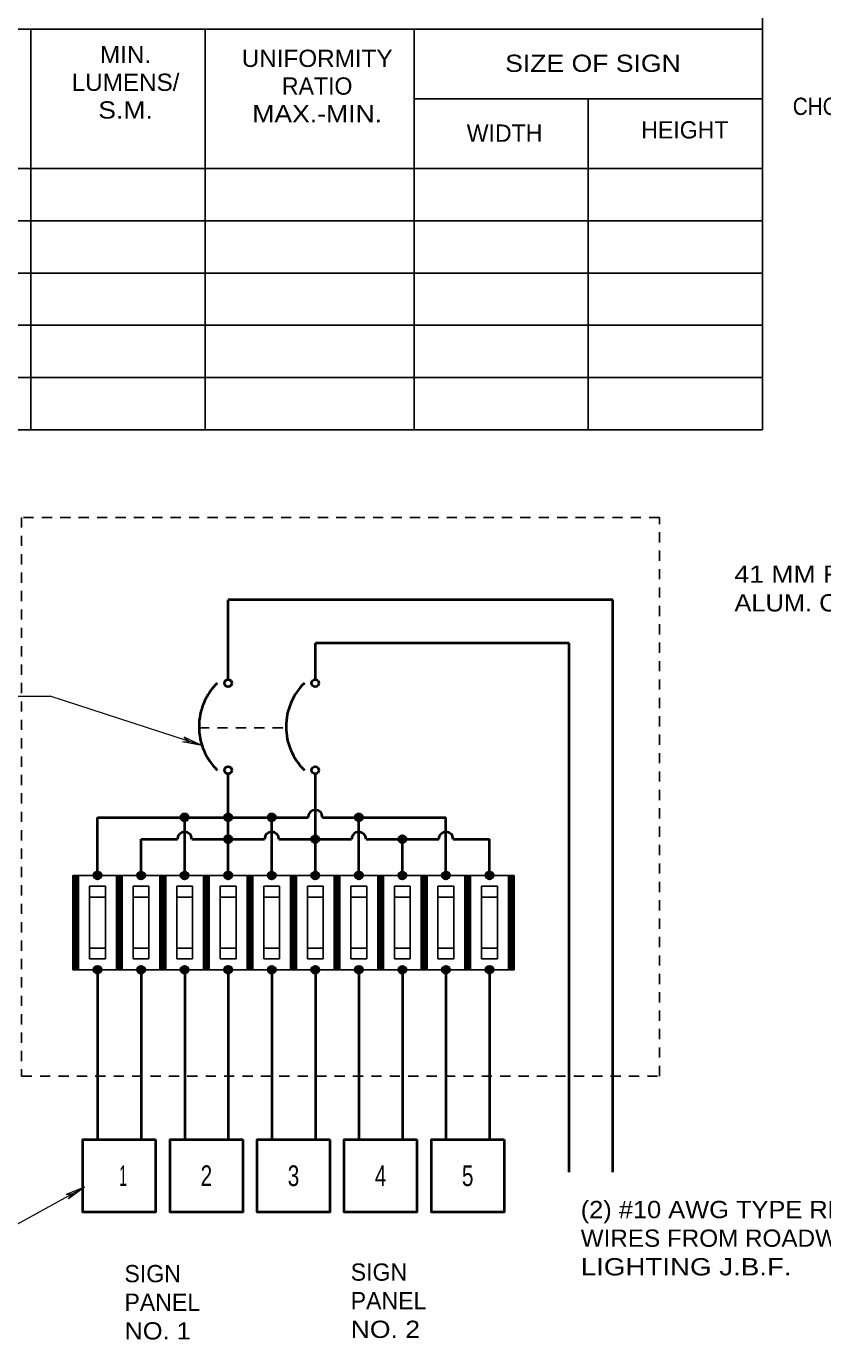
# Model space of a CAD drawing. Extents: x 312583 to 312854, y 144419 to 144597.
# Drawn here: x 312640.4 to 312675.5, y 144479 to 144536.8 of the extents above; entities that cross this region are included whole.
import ezdxf
from ezdxf.enums import TextEntityAlignment as Align

# ---------------------------------------------------------------- set-up
doc = ezdxf.new("R2010")
doc.units = 0
doc.header["$LTSCALE"] = 0.3
doc.linetypes.add('SHORT_DASHED', pattern=[2.7, 1.5, -1.2])
doc.layers.add('1', color=7, linetype='Continuous', lineweight=13)

msp = doc.modelspace()

# ---------------------------------------------------------------- linework, layer by layer
at = {"layer": '1', "lineweight": 25}
for p, q in [((312672.8219, 144540.3271), (312672.8219, 144519.0521)), ((312623.7553, 144536.6855), (312672.8219, 144536.6855)), ((312640.6219, 144536.6855), (312640.6219, 144519.0521)), ((312648.2886, 144536.6855), (312648.2886, 144519.0521)), ((312657.4886, 144536.6855), (312657.4886, 144519.0521)), ((312657.4886, 144533.6188), (312672.8219, 144533.6188)), ((312665.1553, 144533.6188), (312665.1553, 144519.0521)), ((312623.7553, 144530.5521), (312672.8219, 144530.5521)), ((312623.7553, 144528.2521), (312672.8219, 144528.2521)), ((312623.7553, 144525.9521), (312672.8219, 144525.9521)), ((312623.7553, 144523.6521), (312672.8219, 144523.6521)), ((312623.7553, 144521.3521), (312672.8219, 144521.3521)), ((312623.7553, 144519.0521), (312672.8219, 144519.0521)), ((312642.4699, 144499.4355), (312652.3062, 144499.4355)), ((312642.4699, 144495.2802), (312642.4699, 144499.4355)), ((312642.5312, 144495.2802), (312642.5312, 144499.4355)), ((312642.6002, 144495.2802), (312642.6002, 144499.4355)), ((312642.6615, 144495.2802), (312642.6615, 144499.4355)), ((312642.7229, 144495.2802), (312642.7229, 144499.4355)), ((312644.3865, 144495.2802), (312644.3865, 144499.4355)), ((312644.4479, 144495.2802), (312644.4479, 144499.4355)), ((312644.5169, 144495.2802), (312644.5169, 144499.4355)), ((312644.5782, 144495.2802), (312644.5782, 144499.4355)), ((312644.6395, 144495.2802), (312644.6395, 144499.4355)), ((312646.3032, 144495.2802), (312646.3032, 144499.4355)), ((312646.3645, 144495.2802), (312646.3645, 144499.4355)), ((312646.4335, 144495.2802), (312646.4335, 144499.4355)), ((312646.4949, 144495.2802), (312646.4949, 144499.4355)), ((312646.5562, 144495.2802), (312646.5562, 144499.4355)), ((312648.2199, 144495.2802), (312648.2199, 144499.4355)), ((312648.2812, 144495.2802), (312648.2812, 144499.4355)), ((312648.3502, 144495.2802), (312648.3502, 144499.4355)), ((312648.4115, 144495.2802), (312648.4115, 144499.4355)), ((312648.4729, 144495.2802), (312648.4729, 144499.4355)), ((312650.1365, 144495.2802), (312650.1365, 144499.4355)), ((312650.1979, 144495.2802), (312650.1979, 144499.4355)), ((312650.2669, 144495.2802), (312650.2669, 144499.4355)), ((312650.3282, 144495.2802), (312650.3282, 144499.4355)), ((312650.3895, 144495.2802), (312650.3895, 144499.4355)), ((312652.0532, 144495.2802), (312652.0532, 144499.4355)), ((312652.0532, 144499.4355), (312661.8895, 144499.4355)), ((312652.1145, 144495.2802), (312652.1145, 144499.4355)), ((312652.1835, 144495.2802), (312652.1835, 144499.4355)), ((312652.2449, 144495.2802), (312652.2449, 144499.4355)), ((312652.3062, 144495.2802), (312652.3062, 144499.4355)), ((312653.9699, 144495.2802), (312653.9699, 144499.4355)), ((312654.0312, 144495.2802), (312654.0312, 144499.4355)), ((312654.1002, 144495.2802), (312654.1002, 144499.4355)), ((312654.1615, 144495.2802), (312654.1615, 144499.4355)), ((312654.2229, 144495.2802), (312654.2229, 144499.4355)), ((312655.8865, 144495.2802), (312655.8865, 144499.4355)), ((312655.9479, 144495.2802), (312655.9479, 144499.4355)), ((312656.0169, 144495.2802), (312656.0169, 144499.4355)), ((312656.0782, 144495.2802), (312656.0782, 144499.4355)), ((312656.1395, 144495.2802), (312656.1395, 144499.4355)), ((312657.8032, 144495.2802), (312657.8032, 144499.4355)), ((312657.8645, 144495.2802), (312657.8645, 144499.4355)), ((312657.9335, 144495.2802), (312657.9335, 144499.4355)), ((312657.9949, 144495.2802), (312657.9949, 144499.4355)), ((312658.0562, 144495.2802), (312658.0562, 144499.4355)), ((312659.7199, 144495.2802), (312659.7199, 144499.4355)), ((312659.7812, 144495.2802), (312659.7812, 144499.4355)), ((312659.8502, 144495.2802), (312659.8502, 144499.4355)), ((312659.9115, 144495.2802), (312659.9115, 144499.4355)), ((312659.9729, 144495.2802), (312659.9729, 144499.4355)), ((312661.6365, 144495.2802), (312661.6365, 144499.4355)), ((312661.6979, 144495.2802), (312661.6979, 144499.4355)), ((312661.7669, 144495.2802), (312661.7669, 144499.4355)), ((312661.8282, 144495.2802), (312661.8282, 144499.4355)), ((312661.8895, 144495.2802), (312661.8895, 144499.4355)), ((312643.2059, 144498.9602), (312643.9035, 144498.9602)), ((312643.2059, 144495.7632), (312643.2059, 144498.9602)), ((312643.9035, 144495.7632), (312643.9035, 144498.9602)), ((312645.1225, 144498.9602), (312645.8202, 144498.9602)), ((312645.1225, 144495.7632), (312645.1225, 144498.9602)), ((312645.8202, 144495.7632), (312645.8202, 144498.9602)), ((312647.0392, 144498.9602), (312647.7369, 144498.9602)), ((312647.0392, 144495.7632), (312647.0392, 144498.9602)), ((312647.7369, 144495.7632), (312647.7369, 144498.9602)), ((312648.9559, 144498.9602), (312649.6535, 144498.9602)), ((312648.9559, 144495.7632), (312648.9559, 144498.9602)), ((312649.6535, 144495.7632), (312649.6535, 144498.9602)), ((312650.8725, 144498.9602), (312651.5702, 144498.9602)), ((312650.8725, 144495.7632), (312650.8725, 144498.9602)), ((312651.5702, 144495.7632), (312651.5702, 144498.9602)), ((312652.7892, 144498.9602), (312653.4869, 144498.9602)), ((312652.7892, 144495.7632), (312652.7892, 144498.9602)), ((312653.4869, 144495.7632), (312653.4869, 144498.9602)), ((312654.7059, 144498.9602), (312655.4035, 144498.9602)), ((312654.7059, 144495.7632), (312654.7059, 144498.9602)), ((312655.4035, 144495.7632), (312655.4035, 144498.9602)), ((312656.6225, 144498.9602), (312657.3202, 144498.9602)), ((312656.6225, 144495.7632), (312656.6225, 144498.9602)), ((312657.3202, 144495.7632), (312657.3202, 144498.9602)), ((312658.5392, 144498.9602), (312659.2369, 144498.9602)), ((312658.5392, 144495.7632), (312658.5392, 144498.9602)), ((312659.2369, 144495.7632), (312659.2369, 144498.9602)), ((312660.4559, 144498.9602), (312661.1535, 144498.9602)), ((312660.4559, 144495.7632), (312660.4559, 144498.9602)), ((312661.1535, 144495.7632), (312661.1535, 144498.9602)), ((312643.2059, 144498.4772), (312643.9035, 144498.4772)), ((312645.1225, 144498.4772), (312645.8202, 144498.4772)), ((312647.0392, 144498.4772), (312647.7369, 144498.4772)), ((312648.9559, 144498.4772), (312649.6535, 144498.4772)), ((312650.8725, 144498.4772), (312651.5702, 144498.4772)), ((312652.7892, 144498.4772), (312653.4869, 144498.4772)), ((312654.7059, 144498.4772), (312655.4035, 144498.4772)), ((312656.6225, 144498.4772), (312657.3202, 144498.4772)), ((312658.5392, 144498.4772), (312659.2369, 144498.4772)), ((312660.4559, 144498.4772), (312661.1535, 144498.4772)), ((312643.2059, 144496.2385), (312643.9035, 144496.2385)), ((312645.1225, 144496.2385), (312645.8202, 144496.2385)), ((312647.0392, 144496.2385), (312647.7369, 144496.2385)), ((312648.9559, 144496.2385), (312649.6535, 144496.2385)), ((312650.8725, 144496.2385), (312651.5702, 144496.2385)), ((312652.7892, 144496.2385), (312653.4869, 144496.2385)), ((312654.7059, 144496.2385), (312655.4035, 144496.2385)), ((312656.6225, 144496.2385), (312657.3202, 144496.2385)), ((312658.5392, 144496.2385), (312659.2369, 144496.2385)), ((312660.4559, 144496.2385), (312661.1535, 144496.2385)), ((312643.2059, 144495.7632), (312643.9035, 144495.7632)), ((312645.1225, 144495.7632), (312645.8202, 144495.7632)), ((312647.0392, 144495.7632), (312647.7369, 144495.7632)), ((312648.9559, 144495.7632), (312649.6535, 144495.7632)), ((312650.8725, 144495.7632), (312651.5702, 144495.7632)), ((312652.7892, 144495.7632), (312653.4869, 144495.7632)), ((312654.7059, 144495.7632), (312655.4035, 144495.7632)), ((312656.6225, 144495.7632), (312657.3202, 144495.7632)), ((312658.5392, 144495.7632), (312659.2369, 144495.7632)), ((312660.4559, 144495.7632), (312661.1535, 144495.7632)), ((312642.4699, 144495.2802), (312652.3062, 144495.2802)), ((312652.0532, 144495.2802), (312661.8895, 144495.2802))]:
    msp.add_line(p, q, dxfattribs=at)
at = {"layer": '1', "linetype": 'SHORT_DASHED', "lineweight": 25}
for p, q in [((312668.2835, 144490.6035), (312668.2835, 144515.1982)), ((312648.0205, 144505.9292), (312651.8539, 144505.9292)), ((312640.2159, 144490.6035), (312668.2835, 144490.6035))]:
    msp.add_line(p, q, dxfattribs=at)
at = {"layer": '1', "lineweight": 40}
for p, q in [((312649.3085, 144508.0605), (312649.3085, 144511.5718)), ((312666.2365, 144511.5718), (312649.3085, 144511.5718)), ((312666.2365, 144486.3715), (312666.2365, 144511.5718)), ((312653.1419, 144508.0605), (312653.1419, 144509.6552)), ((312664.3199, 144509.6552), (312653.1419, 144509.6552)), ((312664.3199, 144486.3715), (312664.3199, 144509.6552)), ((312649.3085, 144501.9885), (312649.3085, 144503.9052)), ((312649.3085, 144501.0302), (312649.3085, 144503.9052)), ((312653.1419, 144499.4355), (312653.1419, 144503.9052)), ((312643.5585, 144501.9885), (312649.3085, 144501.9885)), ((312643.5585, 144499.4355), (312643.5585, 144501.9885)), ((312647.2309, 144501.9885), (312647.5452, 144501.9885)), ((312647.2769, 144501.8812), (312647.4992, 144502.1035)), ((312647.4992, 144501.8812), (312647.2769, 144502.1035)), ((312647.3919, 144501.8352), (312647.3919, 144502.1495)), ((312647.3919, 144499.4355), (312647.3919, 144501.9885)), ((312649.1475, 144501.9885), (312649.4619, 144501.9885)), ((312649.1935, 144501.8812), (312649.4159, 144502.1035)), ((312649.4159, 144501.8812), (312649.1935, 144502.1035)), ((312649.3085, 144501.8352), (312649.3085, 144502.1495)), ((312649.3085, 144501.9885), (312652.8199, 144501.9885)), ((312651.0642, 144501.9885), (312651.3785, 144501.9885)), ((312651.1102, 144501.8812), (312651.3325, 144502.1035)), ((312651.3325, 144501.8812), (312651.1102, 144502.1035)), ((312651.2252, 144501.8352), (312651.2252, 144502.1495)), ((312651.2252, 144499.4355), (312651.2252, 144501.9885)), ((312653.4562, 144501.9885), (312658.8919, 144501.9885)), ((312654.8975, 144501.9885), (312655.2119, 144501.9885)), ((312654.9435, 144501.8812), (312655.1659, 144502.1035)), ((312655.1659, 144501.8812), (312654.9435, 144502.1035)), ((312655.0585, 144501.8352), (312655.0585, 144502.1495)), ((312655.0585, 144499.4355), (312655.0585, 144501.9885)), ((312658.8919, 144499.4355), (312658.8919, 144501.9885)), ((312649.1935, 144500.9228), (312649.4159, 144501.1452)), ((312649.4159, 144500.9228), (312649.1935, 144501.1452)), ((312649.3085, 144500.8768), (312649.3085, 144501.1912)), ((312653.0269, 144500.9228), (312653.2492, 144501.1452)), ((312653.2492, 144500.9228), (312653.0269, 144501.1452)), ((312653.1419, 144500.8768), (312653.1419, 144501.1912)), ((312656.8602, 144500.9228), (312657.0825, 144501.1452)), ((312657.0825, 144500.9228), (312656.8602, 144501.1452)), ((312656.9752, 144500.8768), (312656.9752, 144501.1912)), ((312645.4752, 144499.4355), (312645.4752, 144501.0302)), ((312645.4752, 144501.0302), (312647.0699, 144501.0302)), ((312647.7062, 144501.0302), (312650.9032, 144501.0302)), ((312649.1475, 144501.0302), (312649.4619, 144501.0302)), ((312649.3085, 144499.4355), (312649.3085, 144501.0302)), ((312651.5395, 144501.0302), (312654.7365, 144501.0302)), ((312652.9809, 144501.0302), (312653.2952, 144501.0302)), ((312655.3729, 144501.0302), (312658.5699, 144501.0302)), ((312656.8142, 144501.0302), (312657.1285, 144501.0302)), ((312656.9752, 144499.4355), (312656.9752, 144501.0302)), ((312659.2062, 144501.0302), (312660.8085, 144501.0302)), ((312660.8085, 144499.4355), (312660.8085, 144501.0302)), ((312643.3975, 144499.4355), (312643.7119, 144499.4355)), ((312643.4435, 144499.3205), (312643.6659, 144499.5505)), ((312643.6659, 144499.3205), (312643.4435, 144499.5505)), ((312643.5585, 144499.2745), (312643.5585, 144499.5965)), ((312645.3142, 144499.4355), (312645.6285, 144499.4355)), ((312645.3602, 144499.3205), (312645.5825, 144499.5505)), ((312645.5825, 144499.3205), (312645.3602, 144499.5505)), ((312645.4752, 144499.2745), (312645.4752, 144499.5965)), ((312647.2309, 144499.4355), (312647.5452, 144499.4355)), ((312647.2769, 144499.3205), (312647.4992, 144499.5505)), ((312647.4992, 144499.3205), (312647.2769, 144499.5505)), ((312647.3919, 144499.2745), (312647.3919, 144499.5965)), ((312649.1475, 144499.4355), (312649.4619, 144499.4355)), ((312649.1935, 144499.3205), (312649.4159, 144499.5505)), ((312649.4159, 144499.3205), (312649.1935, 144499.5505)), ((312649.3085, 144499.2745), (312649.3085, 144499.5965)), ((312651.0642, 144499.4355), (312651.3785, 144499.4355)), ((312651.1102, 144499.3205), (312651.3325, 144499.5505)), ((312651.3325, 144499.3205), (312651.1102, 144499.5505)), ((312651.2252, 144499.2745), (312651.2252, 144499.5965)), ((312652.9809, 144499.4355), (312653.2952, 144499.4355)), ((312653.0269, 144499.3205), (312653.2492, 144499.5505)), ((312653.2492, 144499.3205), (312653.0269, 144499.5505)), ((312653.1419, 144499.2745), (312653.1419, 144499.5965)), ((312654.8975, 144499.4355), (312655.2119, 144499.4355)), ((312654.9435, 144499.3205), (312655.1659, 144499.5505)), ((312655.1659, 144499.3205), (312654.9435, 144499.5505)), ((312655.0585, 144499.2745), (312655.0585, 144499.5965)), ((312656.8142, 144499.4355), (312657.1285, 144499.4355)), ((312656.8602, 144499.3205), (312657.0825, 144499.5505)), ((312657.0825, 144499.3205), (312656.8602, 144499.5505)), ((312656.9752, 144499.2745), (312656.9752, 144499.5965)), ((312658.7309, 144499.4355), (312659.0452, 144499.4355)), ((312658.7769, 144499.3205), (312658.9992, 144499.5505)), ((312658.9992, 144499.3205), (312658.7769, 144499.5505)), ((312658.8919, 144499.2745), (312658.8919, 144499.5965)), ((312660.6475, 144499.4355), (312660.9619, 144499.4355)), ((312660.6935, 144499.3205), (312660.9159, 144499.5505)), ((312660.9159, 144499.3205), (312660.6935, 144499.5505)), ((312660.8085, 144499.2745), (312660.8085, 144499.5965)), ((312643.4435, 144495.1728), (312643.6659, 144495.3952)), ((312643.6659, 144495.1728), (312643.4435, 144495.3952)), ((312643.5585, 144495.1268), (312643.5585, 144495.4412)), ((312645.3602, 144495.1728), (312645.5825, 144495.3952)), ((312645.5825, 144495.1728), (312645.3602, 144495.3952)), ((312645.4752, 144495.1268), (312645.4752, 144495.4412)), ((312647.2769, 144495.1728), (312647.4992, 144495.3952)), ((312647.4992, 144495.1728), (312647.2769, 144495.3952)), ((312647.3919, 144495.1268), (312647.3919, 144495.4412)), ((312649.1935, 144495.1728), (312649.4159, 144495.3952)), ((312649.4159, 144495.1728), (312649.1935, 144495.3952)), ((312649.3085, 144495.1268), (312649.3085, 144495.4412)), ((312651.1102, 144495.1728), (312651.3325, 144495.3952)), ((312651.3325, 144495.1728), (312651.1102, 144495.3952)), ((312651.2252, 144495.1268), (312651.2252, 144495.4412)), ((312653.0269, 144495.1728), (312653.2492, 144495.3952)), ((312653.2492, 144495.1728), (312653.0269, 144495.3952)), ((312653.1419, 144495.1268), (312653.1419, 144495.4412)), ((312654.9435, 144495.1728), (312655.1659, 144495.3952)), ((312655.1659, 144495.1728), (312654.9435, 144495.3952)), ((312655.0585, 144495.1268), (312655.0585, 144495.4412)), ((312656.8602, 144495.1728), (312657.0825, 144495.3952)), ((312657.0825, 144495.1728), (312656.8602, 144495.3952)), ((312656.9752, 144495.1268), (312656.9752, 144495.4412)), ((312658.7769, 144495.1728), (312658.9992, 144495.3952)), ((312658.9992, 144495.1728), (312658.7769, 144495.3952)), ((312658.8919, 144495.1268), (312658.8919, 144495.4412)), ((312660.6935, 144495.1728), (312660.9159, 144495.3952)), ((312660.9159, 144495.1728), (312660.6935, 144495.3952)), ((312660.8085, 144495.1268), (312660.8085, 144495.4412)), ((312643.3975, 144495.2802), (312643.7119, 144495.2802)), ((312643.5585, 144495.2802), (312643.5585, 144487.8052)), ((312645.3142, 144495.2802), (312645.6285, 144495.2802)), ((312645.4752, 144495.2802), (312645.4752, 144487.8052)), ((312647.2309, 144495.2802), (312647.5452, 144495.2802)), ((312647.3919, 144495.2802), (312647.3919, 144487.8052)), ((312649.1475, 144495.2802), (312649.4619, 144495.2802)), ((312649.3085, 144495.2802), (312649.3085, 144487.8052)), ((312651.0642, 144495.2802), (312651.3785, 144495.2802)), ((312651.2252, 144495.2802), (312651.2252, 144487.8052)), ((312652.9809, 144495.2802), (312653.2952, 144495.2802)), ((312653.1419, 144495.2802), (312653.1419, 144487.8052)), ((312654.8975, 144495.2802), (312655.2119, 144495.2802)), ((312655.0585, 144495.2802), (312655.0585, 144487.8052)), ((312656.8142, 144495.2802), (312657.1285, 144495.2802)), ((312656.9752, 144495.2802), (312656.9752, 144487.8052)), ((312658.7309, 144495.2802), (312659.0452, 144495.2802)), ((312658.8919, 144495.2802), (312658.8919, 144487.8052)), ((312660.6475, 144495.2802), (312660.9619, 144495.2802)), ((312660.8085, 144495.2802), (312660.8085, 144487.8052))]:
    msp.add_line(p, q, dxfattribs=at)
at = {"layer": '1'}
for p, q in [((312633.5919, 144507.3238), (312641.4655, 144507.3238)), ((312648.1509, 144505.1548), (312641.4655, 144507.3238)), ((312647.2999, 144505.3158), (312647.5912, 144505.3312)), ((312648.1509, 144505.1548), (312647.2999, 144505.3158)), ((312647.3612, 144505.5228), (312647.5912, 144505.3312)), ((312648.1509, 144505.1548), (312647.3612, 144505.5228)), ((312642.9835, 144485.7122), (312638.5675, 144483.2742)), ((312642.9835, 144485.7122), (312642.1785, 144485.3902)), ((312642.9835, 144485.7122), (312642.2782, 144485.1985)), ((312642.1785, 144485.3902), (312642.4699, 144485.4285)), ((312642.2782, 144485.1985), (312642.4699, 144485.4285))]:
    msp.add_line(p, q, dxfattribs=at)
at = {"layer": '1', "linetype": 'SHORT_DASHED', "lineweight": 25}
msp.add_lwpolyline([(312668.2835, 144515.1982), (312668.2835, 144515.1982), (312640.2159, 144515.1982), (312640.2159, 144490.6035)], dxfattribs=at)
at = {"layer": '1', "lineweight": 40}
for points in [[(312646.1115, 144487.8052), (312646.1115, 144484.6158), (312642.9145, 144484.6158), (312642.9145, 144487.8052)], [(312649.9449, 144487.8052), (312649.9449, 144484.6158), (312646.7479, 144484.6158), (312646.7479, 144487.8052)], [(312653.7782, 144487.8052), (312653.7782, 144484.6158), (312650.5812, 144484.6158), (312650.5812, 144487.8052)], [(312657.6115, 144487.8052), (312657.6115, 144484.6158), (312654.4145, 144484.6158), (312654.4145, 144487.8052)], [(312661.4449, 144487.8052), (312661.4449, 144484.6158), (312658.2479, 144484.6158), (312658.2479, 144487.8052)]]:
    msp.add_lwpolyline(points, close=True, dxfattribs=at)
for centre in [(312649.3047, 144507.9008), (312653.138, 144507.9008), (312649.3047, 144504.0674), (312653.138, 144504.0674), (312647.388, 144501.9911), (312649.3047, 144501.9911), (312651.2214, 144501.9911), (312655.0547, 144501.9911), (312649.3047, 144501.0327), (312653.138, 144501.0327), (312656.9714, 144501.0327), (312643.5547, 144499.4355), (312645.4714, 144499.4355), (312647.388, 144499.4355), (312649.3047, 144499.4355), (312651.2214, 144499.4355), (312653.138, 144499.4355), (312655.0547, 144499.4355), (312656.9714, 144499.4355), (312658.888, 144499.4355), (312660.8047, 144499.4355), (312643.5547, 144495.2827), (312645.4714, 144495.2827), (312647.388, 144495.2827), (312649.3047, 144495.2827), (312651.2214, 144495.2827), (312653.138, 144495.2827), (312655.0547, 144495.2827), (312656.9714, 144495.2827), (312658.888, 144495.2827), (312660.8047, 144495.2827)]:
    msp.add_circle(centre, 0.1597, dxfattribs=at)
for centre, radius, start, end in [((312650.7067, 144505.9841), 2.6856, 134.46426, 225.53573), ((312654.54, 144505.9841), 2.6856, 134.46426, 225.53573), ((312653.138, 144501.9911), 0.3194, 0, 180), ((312647.388, 144501.0327), 0.3194, 0, 180), ((312651.2214, 144501.0327), 0.3194, 0, 180), ((312655.0547, 144501.0327), 0.3194, 0, 180), ((312658.888, 144501.0327), 0.3194, 0, 180)]:
    msp.add_arc(centre, radius, start, end, dxfattribs=at)

# ---------------------------------------------------------------- texts
at = {"layer": '1'}
for s, height, width, p in [('MIN.', 0.76, 1.05, (312644.7888, 144535.1943)), ('UNIFORMITY', 0.76, 1.05, (312653.2221, 144535.0275)), ('SIZE OF SIGN', 0.76, 1.15, (312665.36, 144534.8092)), ('LUMENS/', 0.76, 1.05, (312644.7888, 144533.9743)), ('S.M.', 0.76, 1.15, (312644.7888, 144532.7543)), ('MAX.-MIN.', 0.76, 1.15, (312653.2221, 144532.5875)), ('1', 0.9104, 0.5, (312644.6817, 144485.7582)), ('2', 0.9104, 0.75, (312648.3463, 144485.7582)), ('3', 0.9104, 0.75, (312652.1797, 144485.7582)), ('4', 0.9104, 0.75, (312656.013, 144485.7582)), ('5', 0.9104, 0.75, (312659.8463, 144485.7582))]:
    msp.add_text(s, height=height, dxfattribs=dict(at, width=width)).set_placement(p, align=Align.CENTER)
for s, p in [('RATIO', (312653.2221, 144533.8075)), ('WIDTH', (312661.4698, 144531.7339)), ('HEIGHT', (312669.4043, 144531.8775))]:
    msp.add_text(s, height=0.76, dxfattribs=at).set_placement(p, align=Align.CENTER)
for s, width, p in [('CHORDS', 0.9, (312674.154, 144532.914)), ('41 MM RIGID', 1.15, (312671.5883, 144512.3161)), ('ALUM. CONDUIT', 1.1, (312671.5883, 144511.0561)), ('(2) #10 AWG TYPE RHW', 1.1, (312664.8213, 144484.3446)), ('WIRES FROM ROADWAY', 1.05, (312664.8213, 144483.0846)), ('LIGHTING J.B.F.', 1.2, (312664.8213, 144481.8246)), ('NO. 1', 1.1, (312644.7401, 144479.0037)), ('NO. 2', 1.15, (312654.6975, 144479.0715))]:
    msp.add_text(s, height=0.76, dxfattribs=dict(at, width=width)).set_placement(p)
for s, p in [('SIGN', (312644.7401, 144481.5237)), ('SIGN', (312654.6975, 144481.5915)), ('PANEL', (312644.7401, 144480.2637)), ('PANEL', (312654.6975, 144480.3315))]:
    msp.add_text(s, height=0.76, dxfattribs=at).set_placement(p)

doc.saveas('drawing.dxf')
